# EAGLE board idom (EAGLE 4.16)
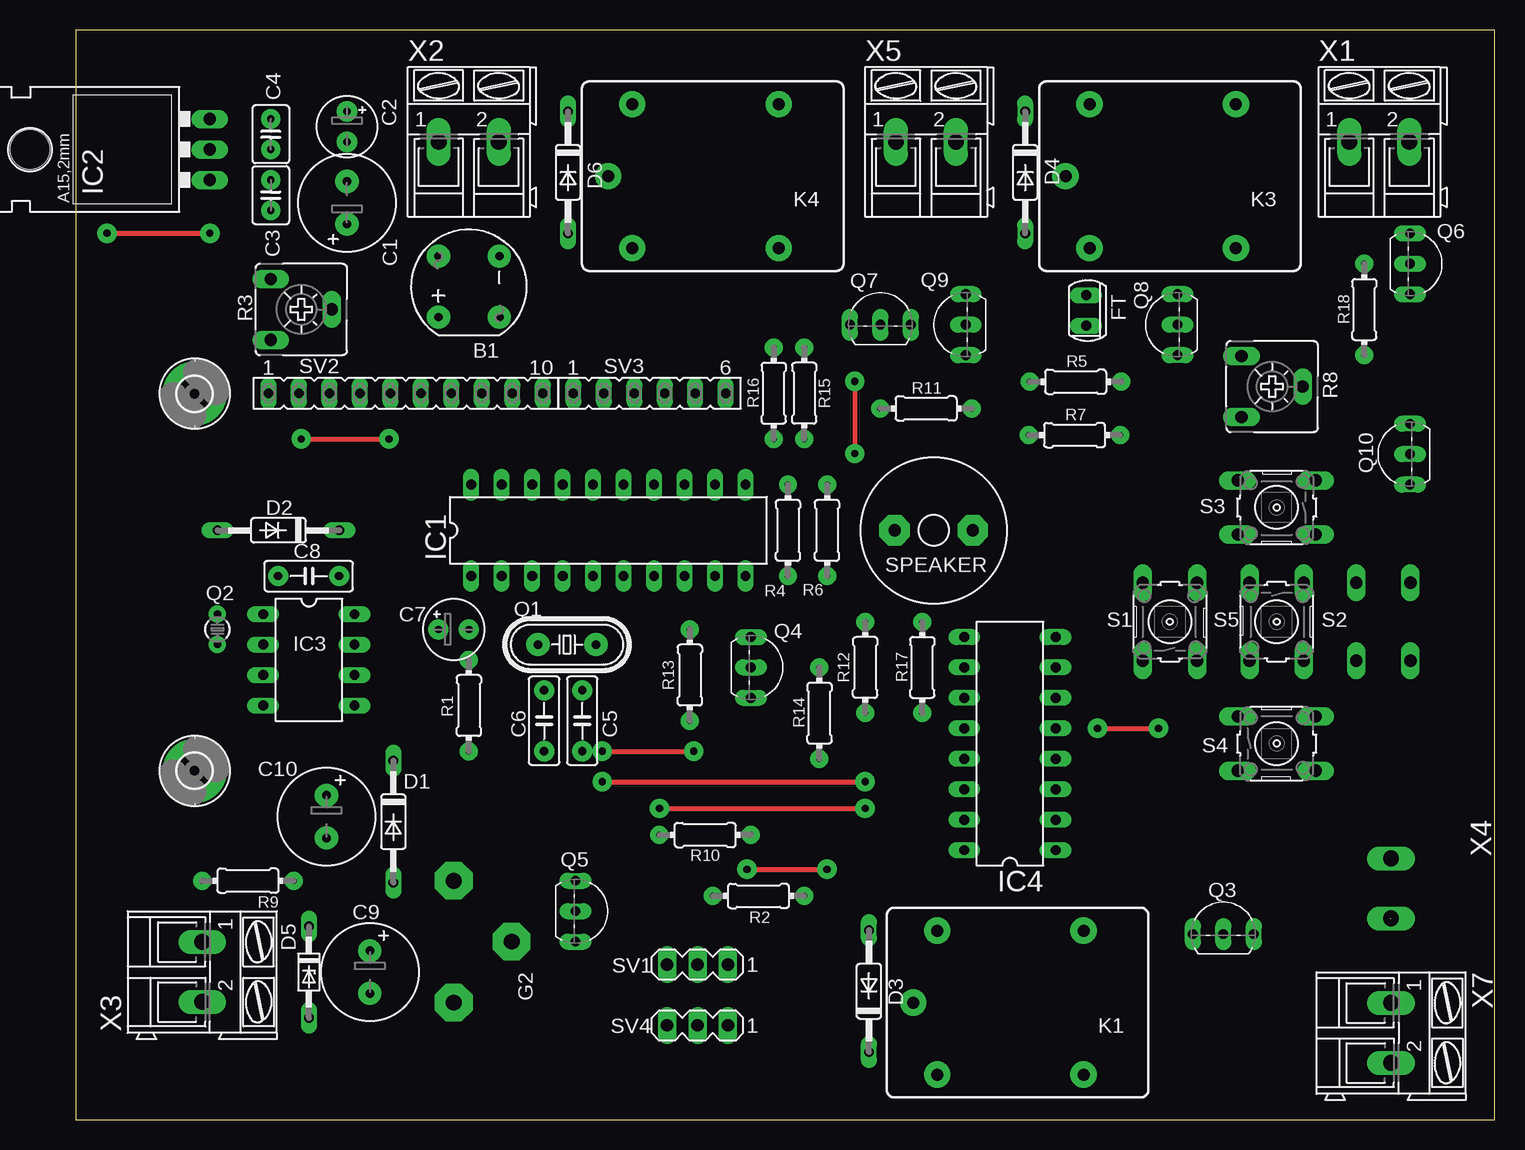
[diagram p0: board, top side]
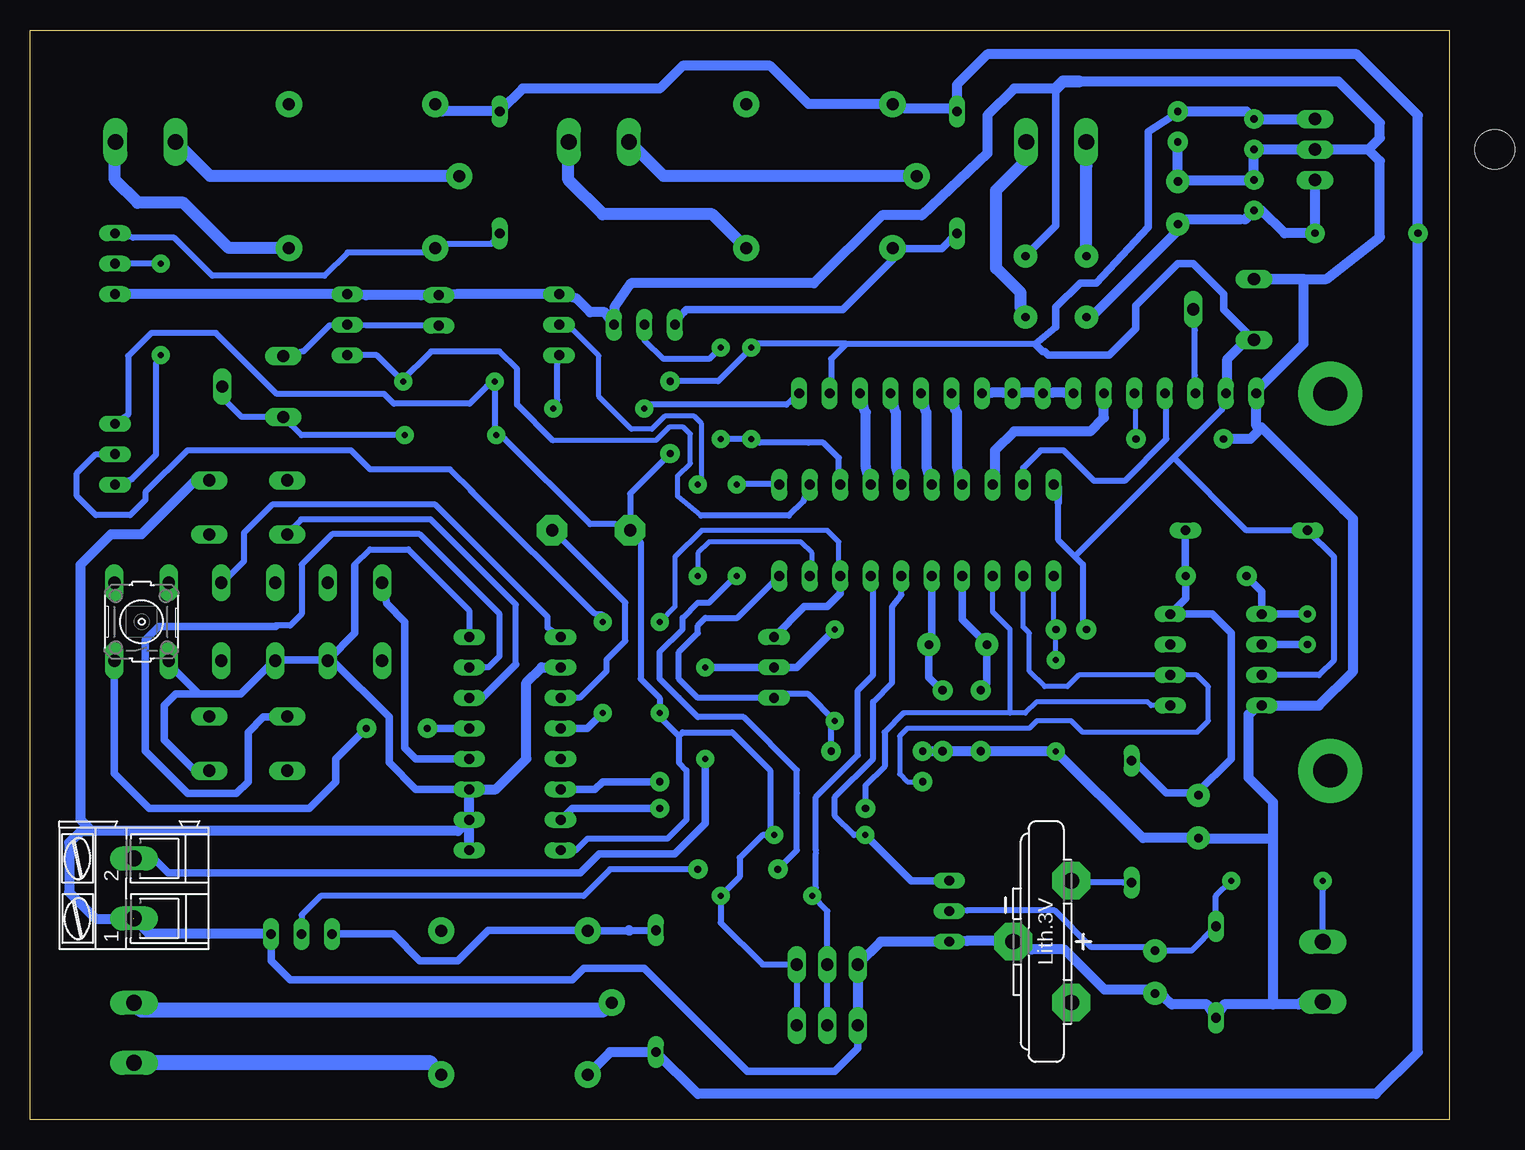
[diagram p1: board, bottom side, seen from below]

Size 118.27 x 90.86 mm. Coordinates in mm from the lower left corner, seen from the top.
Outline: 0,0 118.27,0 118.27,90.86 0,90.86 0,0
Copper layers (1*16): Top 0.035mm / dielectric 1.5mm / Bottom 0.035mm
Design rules "mój": minimum track width 20mil, minimum drill 15mil, track to track 25mil, track to pad 30mil, pad to pad 25mil, via to via 25mil, smd to smd 20mil, copper to edge 20mil, drill to drill 20mil, minimum pad ring 10mil, minimum via ring 20mil, stop-mask expansion 4mil, vias tented up to drill 0mil, thermal gap 10mil
Net classes: 1 1mm: width 1 mm, drill 1 mm; 2 2mm: width 2 mm, drill 2 mm

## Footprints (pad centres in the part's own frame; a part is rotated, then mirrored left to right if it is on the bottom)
2,8-PAD = drill 2.8 pad 5.334 round: B2,8 0,0
RB1A = drill 0.7 pad 1.93 round: + -2.54,2.54; - 2.54,-2.54; AC1 2.54,2.54; AC2 -2.54,-2.54
E3,5-8 = drill 0.7 pad 1.93 round: + -1.778,0; - 1.778,0
E2,5-5 = drill 0.6 pad 1.676 round: + -1.27,0; - 1.27,0
C2.5-3 = drill 0.6 pad 1.6 round: 1 -1.27,0; 2 1.27,0
C5B2.5 = drill 0.7 pad 1.676 round: 1 -2.54,0; 2 2.54,0
DO35-10 = drill 0.813 long: A 5.08,0; C -5.08,0
DO34Z7 = drill 0.813 long: A 3.81,0; C -3.81,0
SFH225 = drill 0.813 long: A 0,1.27; K 0,-1.27
CR2032V = drill 1.321 pad 3.15 octagon: + -2.54,-5.08; +@1 -2.54,5.08; - 2.286,0
DIL20 = drill 0.813 long: 1 -11.43,-3.81; 2 -8.89,-3.81; 3 -6.35,-3.81; 4 -3.81,-3.81; 5 -1.27,-3.81; 6 1.27,-3.81; 7 3.81,-3.81; 8 6.35,-3.81; 9 8.89,-3.81; 10 11.43,-3.81; 11 11.43,3.81; 12 8.89,3.81; 13 6.35,3.81; 14 3.81,3.81; 15 1.27,3.81; 16 -1.27,3.81; 17 -3.81,3.81; 18 -6.35,3.81; 19 -8.89,3.81; 20 -11.43,3.81
78XXL = drill 1.016 long: GND 0,-3.81; IN -2.54,-3.81; OUT 2.54,-3.81 | hole 3.302: 0,11.176
DIL08 = drill 0.813 long: 1 -3.81,-3.81; 2 -1.27,-3.81; 3 1.27,-3.81; 4 3.81,-3.81; 5 3.81,3.81; 6 1.27,3.81; 7 -1.27,3.81; 8 -3.81,3.81
DIL16 = drill 0.813 long: 1 -8.89,-3.81; 2 -6.35,-3.81; 3 -3.81,-3.81; 4 -1.27,-3.81; 5 1.27,-3.81; 6 3.81,-3.81; 7 6.35,-3.81; 8 8.89,-3.81; 9 8.89,3.81; 10 6.35,3.81; 11 3.81,3.81; 12 1.27,3.81; 13 -1.27,3.81; 14 -3.81,3.81; 15 -6.35,3.81; 16 -8.89,3.81
JS-M = drill 1 pad 2.184 round: 1 6.7,6; 2 6.7,-6; C 8.7,0; NC -5.5,-6; NO -5.5,6
HC49/S = drill 0.7 pad 1.93 round: 1 -2.413,0; 2 2.413,0
TC26V = drill 0.6 pad 1.422 round: 1 -1.27,0; 2 1.27,0
TO92-EBC = drill 0.813 long: B 0,-1.27; C -2.54,-1.27; E 2.54,-1.27
0204/7 = drill 0.5 pad 1.499 round: 1 -3.81,0; 2 3.81,0
CA6V = drill 1.016 long: A -2.54,-2.54; E 2.54,-2.54; S 0,2.54
B3F-10XX = drill 1.016 long: 1 -3.251,2.261; 2 3.251,2.261; 3 -3.251,-2.261; 4 3.251,-2.261
AL60P = drill 1.016 pad 2.54 octagon: 1 -3.251,0; 2 3.251,0
MA03-1 = drill 1.016 long: 1 -2.54,0; 2 0,0; 3 2.54,0
FE10 = drill 0.813 long: 1 -11.43,0; 2 -8.89,0; 3 -6.35,0; 4 -3.81,0; 5 -1.27,0; 6 1.27,0; 7 3.81,0; 8 6.35,0; 9 8.89,0; 10 11.43,0
FE06 = drill 0.813 long: 1 -6.35,0; 2 -3.81,0; 3 -1.27,0; 4 1.27,0; 5 3.81,0; 6 6.35,0
AK300/2 = drill 1.321 long: 1 -2.515,0; 2 2.489,0

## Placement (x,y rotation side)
.  [2,8-PAD]  9.91,60.53 0 top
B1  mostek 1A  [RB1A]  32.77,69.46 90 top
C1  470uF  [E3,5-8]  22.61,76.45 90 top
C2  100uF  [E2,5-5]  22.61,82.8 270 top
C3  100nF  [C2.5-3]  16.27,77.08 90 top
C4  100nF  [C2.5-3]  16.27,82.16 270 top
C5  33pF  [C5B2.5]  42.22,33.27 90 top
C6  33pF  [C5B2.5]  39.05,33.27 90 top
C7  10uF  [E2,5-5]  31.5,40.89 0 top
C8  33pF  [C5B2.5]  19.42,45.33 0 top
C9  10uF  [E3,5-8]  24.52,12.31 270 top
C10  22uF  [E3,5-8]  20.9,25.27 270 top
D1  1N4148  [DO35-10]  26.47,24.85 270 top
D2  1N4148  [DO35-10]  16.9,49.14 180 top
D3  1N4148  [DO35-10]  66.11,10.73 90 top
D4  1N4148  [DO35-10]  79.13,78.99 270 top
D5  4.7V  [DO34Z7]  19.44,12.31 270 top
D6  1N4148  [DO35-10]  41.03,78.99 270 top
FT  fotorezystor  [SFH225]  84.21,67.48 0 top
G2  CR2032V  [CR2032V]  34.05,14.85 180 bottom
IC1  AT89C4051P  [DIL20]  44.39,49.14 0 top
IC2  7805  [78XXL]  7.37,80.89 90 top
IC3  PFC8583P  [DIL08]  19.44,38.35 270 top
IC4  PCF8574AP  [DIL16]  77.86,31.36 90 top
K1  JQC-3FF  [JS-M]  78.5,9.77 180 top
K3  JQC-3FF  [JS-M]  91.19,78.67 180 top
K4  JQC-3FF  [JS-M]  53.09,78.67 180 top
Q1  11.059MHz  [HC49/S]  40.95,39.62 0 top
Q2  32768 Hz  [TC26V]  11.82,40.89 90 top
Q3  BC548  [TO92-EBC]  95.64,16.76 0 top
Q4  BC548  [TO92-EBC]  57.54,37.71 270 top
Q5  BC548  [TO92-EBC]  42.94,17.39 270 top
Q6  BC548  [TO92-EBC]  112.47,71.37 270 top
Q7  BC548  [TO92-EBC]  67.06,67.56 0 top
Q8  BC548  [TO92-EBC]  90.56,66.29 90 top
Q9  BC337  [TO92-EBC]  72.91,66.29 90 top
Q10  BC560  [TO92-EBC]  109.93,55.49 90 top
R1  10K  [0204/7]  32.77,34.54 90 top
R2  4.7K  [0204/7]  56.91,18.66 180 top
R3  10K  [CA6V]  18.8,67.56 270 top
R4  4.7K  [0204/7]  59.37,49.14 90 top
R5  1K  [0204/7]  83.34,61.53 180 top
R6  4.7K  [0204/7]  62.62,49.14 90 top
R7  100K (dobrac)  [0204/7]  83.24,57.08 180 top
R8  10K  [CA6V]  99.7,61.13 270 top
R9  4.7K  [0204/7]  14.36,19.93 180 top
R10  1K  [0204/7]  52.46,23.74 0 top
R11  9ohm lub zworka  [0204/7]  70.88,59.3 180 top
R12  1K  [0204/7]  65.8,37.71 90 top
R13  4.7K  [0204/7]  51.19,37.08 90 top
R14  10K  [0204/7]  61.98,33.9 270 top
R15  4.7K  [0204/7]  60.71,60.57 90 top
R16  1K  [0204/7]  58.17,60.57 270 top
R17  2.2K  [0204/7]  70.56,37.71 270 top
R18  2.2K  [0204/7]  107.39,67.56 270 top
S1  Prev  [B3F-10XX]  91.19,41.52 90 top
S2  Next  [B3F-10XX]  108.97,41.52 90 bottom
S3  plus  [B3F-10XX]  100.09,51.05 180 top
S4  minus  [B3F-10XX]  100.09,31.36 0 top
S5  OK  [B3F-10XX]  100.09,41.52 270 top
SPEAKER  AL60P  [AL60P]  71.51,49.14 180 top
SV1  termometr wewn.  [MA03-1]  51.82,12.95 180 top
SV2  [FE10]  27.5,60.57 0 top
SV3  [FE06]  47.82,60.57 0 top
SV4  termometr zewn.  [MA03-1]  51.82,7.87 180 top
X1  [AK300/2]  108.66,81.53 0 top
X2  [AK300/2]  32.77,81.53 0 top
X3  [AK300/2]  10.55,12.31 270 top
X4  [AK300/2]  109.61,19.3 90 bottom
X5  [AK300/2]  70.88,81.53 0 top
X7  [AK300/2]  109.61,7.23 270 top
~  [2,8-PAD]  9.91,29.1 0 top

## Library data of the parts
. ~ = holes
B1 = rectifier
C1 C2 C7 C9 C10 R1 R2 R4-R7 R9-R18 = rcl
C3-C6 C8 = capacitor-wima
D1-D6 = diode
FT = opto-trans-siemens
G2 = battery
IC1 = atmel
IC2 = v-reg
IC3 IC4 = micro-philips
K1 K3 K4 = relay
Q1 Q2 = crystal
Q3-Q9 = transistor-npn
Q10 = transistor-pnp
R3 R8 = pot
S1-S5 = switch-omron
SPEAKER = buzzer
SV1 SV4 = con-lstb
SV2 SV3 = con-lsta
X1-X5 X7 = con-ptr500

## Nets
N$1: D6.A K4.1 Q7.C
N$2: IC1.19 SV2.4
N$3: IC1.18 SV2.6
N$4: IC1.12 Q8.C R5.1
N$5: IC1.17 SV3.1
N$6: C5.2 IC1.5 Q1.2
N$7: C6.2 IC1.4 Q1.1
N$8: IC1.16 SV3.2
N$9: C7.- IC1.1 R1.2
N$10: IC1.15 SV3.3
N$11: IC1.14 SV3.4
N$12: SV2.7 SV2.8 SV2.9 SV2.10
N$13: R3.S SV2.3
N$14: IC3.2 Q2.1
N$15: C8.1 IC3.1 Q2.2
N$16: Q3.B R4.1
N$17: D1.A G2.+
N$18: C8.2 C10.+ D1.C D2.C IC3.8
N$19: IC1.11 R4.2
N$20: IC1.2 IC3.6 IC4.14
N$21: IC1.3 IC3.5 IC4.15
N$22: D3.A K1.2 Q3.C
N$23: Q9.B R6.2
N$24: IC1.9 R6.1
N$25: Q9.C R11.1
N$26 [1mm]: K1.C X7.1
N$27 [1mm]: K1.NO X7.2
N$28 [1mm]: K3.C X1.1
N$29: IC4.4 S1.2
N$30 [1mm]: B1.AC1 X2.1
N$31 [1mm]: B1.AC2 X2.2
N$32: IC4.5 S2.1
N$33: IC4.6 S3.2
N$34: IC4.7 S4.1
N$35: IC4.9 S5.1
N$36: R11.2 SV3.6
N$37: R7.1 R8.E R8.S
N$38: IC1.7 R2.2 SV1.2 SV4.2
N$39: IC1.8 Q4.C R12.2
N$40: IC1.6 Q5.C R10.1
N$41: C9.+ D5.C Q5.B R9.1
N$42: Q4.B R13.2 R14.1
N$43: R9.2 X3.1
N$44: C2.+ C4.1 C7.+ D2.A IC1.20 IC2.OUT IC3.3 IC4.16 Q10.E R2.1 R3.E R5.2 R7.2 R10.2 R12.1 R16.1 SPEAKER.2 SV1.1 SV2.2 SV3.5 SV4.1
N$45: R14.2 X4.2
N$46: B1.+ C1.+ C3.1 D3.C D4.C D6.C IC2.IN K1.1 K3.2 K4.2
N$47: B1.- C1.- C2.- C3.2 C4.2 C5.1 C6.1 C9.- C10.- D5.A FT.A G2.- IC1.10 IC2.GND IC3.4 IC4.1 IC4.2 IC4.3 IC4.8 IC4.10 Q3.E Q4.E Q5.E Q6.E Q7.E Q8.E Q9.E R1.1 R3.A R13.1 S1.3 S2.3 S3.3 S4.4 S5.4 SV1.3 SV2.1 SV2.5 SV4.3 X3.2 X4.1
N$48: Q7.B R15.2
N$49 [1mm]: K4.NO X5.2
N$50 [1mm]: K4.C X5.1
N$51: IC1.13 R15.1 R16.2
N$52: IC4.12 R17.2
N$53: FT.K Q8.B R8.A
N$54: Q10.B R17.1
N$55 [1mm]: K3.NO X1.2
N$56: Q10.C R18.2
N$57: Q6.B R18.1
N$58: D4.A K3.1 Q6.C
N$59: IC4.11 SPEAKER.1

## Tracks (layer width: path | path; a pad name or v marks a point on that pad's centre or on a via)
N$1
  Bottom 0.508: 63.76,67.33 Q7.C
  Bottom 0.61: D6.A 42.3,72.64 46.36,72.64 K4.1 46.39,71.72 50.55,67.56 63.57,67.56 63.76,67.37 63.76,67.33
N$2
  Bottom 0.406: 23.57,60.57 SV2.4
  Bottom 0.508: IC1.19 35.5,54.35 34.05,55.81 32.14,55.81 29.6,53.27 27.06,53.27 23.57,56.76 23.57,60.57
N$3
  Bottom 0.813: SV2.6 28.77,58.54 29.92,57.4 36.27,57.4 37.86,55.81 37.86,52.95 IC1.18
N$4
  Bottom 0.406: 77.66,59.62 77.67,59.61 77.68,59.61 | 62.38,50.36 64.31,51.98 64.31,53.7 63.25,54.73 63.25,57.18 63.82,57.75 65.01,57.75 66.11,56.65 74.69,56.65 | 87.38,61.53 R5.1
  Bottom 0.508: IC1.12 53.81,51.58 55.02,50.36 62.38,50.36 | 74.69,56.65 77.66,59.62 | 77.68,59.61 77.68,62.62 79.13,64.07 84.84,64.07 87.38,61.53 | R5.1 89.37,63.75 Q8.C
N$5
  Bottom 0.508: 41,59 41.11,59.1
  Bottom 0.813: 41,59 41,54.43 IC1.17 | 41.11,59.1 SV3.1
N$6
  Bottom 0.406: Q1.2 43.25,39.62 43.12,39.75 | C5.2 42.3,35.81
  Bottom 0.61: 43.12,39.75 IC1.5 | Q1.2 43.36,36.87 42.3,35.81
N$7
  Bottom 0.406: Q1.1 38.49,39.62 | C6.2 39.12,35.81
  Bottom 0.61: IC1.4 40.59,41.71 38.49,39.62 | Q1.1 38.54,36.4 39.12,35.81
N$8
  Bottom 0.508: 43.55,59 43.65,59.1
  Bottom 0.813: 43.55,59 43.55,54.43 IC1.16 | 43.65,59.1 SV3.2
N$9
  Bottom 0.406: IC1.1 32.97,41.02 33.09,40.89 C7.- R1.2
N$10
  Bottom 0.508: 46.09,59 46.19,59.1
  Bottom 0.813: 46.09,59 46.09,54.43 IC1.15 | 46.19,59.1 SV3.3
N$11
  Bottom 0.508: 48.62,59 48.73,59.1
  Bottom 0.813: 48.62,59 48.62,54.43 IC1.14 | 48.73,59.1 SV3.4
N$12
  Bottom 0.813: SV2.7 32.06,60.62 33.08,60.62 SV2.8 34.6,60.62 35.62,60.62 SV2.9 37.14,60.62 38.16,60.62 SV2.10
N$13
  Bottom 0.508: SV2.3 21.19,62.05 21.19,65.81 R3.S
N$14
  Bottom 0.61: Q2.1 IC3.2
N$15
  Bottom 0.406: 16.9,45.33 C8.1
  Bottom 0.61: Q2.2 IC3.1 15.63,44.06 16.9,45.33
N$16  (via drill 0.6)
  Top 0.406: v55.95,20.89 v62.62,20.89
  Bottom 0.406: 59.45,45.33 R4.1
  Bottom 0.508: v62.62,20.89 69.92,20.89 72.14,18.66 94.05,18.66 95.64,17.08 Q3.B | 59.45,45.33 61.67,43.11 62.62,43.11 63.89,41.84 63.89,40.89 65.8,38.98 65.8,36.76 64.21,35.17 62.62,33.59 58.81,33.59 54.37,29.14 54.37,27.24 54.37,22.47 v55.95,20.89
N$17
  Bottom 0.508: D1.A 27.19,19.78 30.03,19.78 G2.+
N$18
  Bottom 0.406: 21.03,27.24 20.91,27.11 C10.+ | 26.43,30.09 26.47,30.05 D1.C | C8.2 21.98,45.33
  Bottom 0.61: 26.43,30.09 23.57,27.24 21.03,27.24 18.17,30.09 18.17,40.57 19.76,42.16 IC3.8 21.96,43.45 C8.2 | 21.98,45.33 D2.C
N$19
  Bottom 0.508: IC1.11 56.55,53.01 58.58,53.01 R4.2
N$20  (via drill 0.6)
  Top 0.406: v43.89,28.19 v65.8,28.19
  Bottom 0.406: IC1.2 35.5,41.08 35,40.57 35,37.4 33.73,36.13 31.82,36.13 30.87,37.08 IC3.6 21.03,37.08 20.07,36.13 20.07,33.27 21.03,32.32 30.55,32.32 31.5,33.27 34.36,33.27 35,32.63 45.16,32.63 45.79,32 45.79,28.82 45.16,28.19 v43.89,28.19
  Bottom 0.61: IC4.14 71.19,27.55 70.56,28.19 v65.8,28.19
N$21  (via drill 0.6)
  Top 0.406: v48.65,25.97 v65.8,25.97
  Bottom 0.406: 36.59,33.9 35.31,33.9 34.36,34.86 25.16,34.86 24.84,34.54 IC3.5 | 36.59,33.9 45.48,33.9 | IC1.3 38.05,42.35 36.59,40.89 36.59,33.9
  Bottom 0.508: 45.48,33.9 47.06,32.32 47.06,29.46 48.65,27.87 v48.65,25.97
  Bottom 0.61: IC4.15 73.1,25.97 v65.8,25.97
N$22
  Bottom 0.61: D3.A 68.3,15.77 | Q3.C 88.02,15.49 85.8,13.27 82.62,13.27 80.08,15.81 71.83,15.81 | 68.37,15.77 K1.2
  Bottom 0.813: K1.2 71.83,15.81 | 68.3,15.77 68.34,15.81 68.37,15.77
N$23
  Bottom 0.406: Q9.B 74.05,66.29 74.01,66.33 73.5,66.33 70.88,63.7 70.88,60.31 68.15,57.58 66.45,57.58 65.37,58.67 62.94,58.67 62.3,58.03 62.3,53.27 R6.2
N$24
  Bottom 0.406: R6.1 62.62,47.24 61.67,48.19 54.05,48.19 53.09,47.24 53.09,45.33 IC1.9
N$25
  Bottom 0.508: Q9.C 74.33,63.06 74.33,60.02 R11.1
N$26
  Bottom 0.813: K1.C 69.92,9.77
  Bottom 1.27: X7.1 109,9.14 70.56,9.14 69.92,9.77
  Bottom 1.422: K1.C 69.6,9.77
N$27
  Bottom 0.813: 83.93,3.77 84.9,4.75
  Bottom 1.27: K1.NO 83.93,3.77 | 84.9,4.75 X7.2
  Bottom 1.422: 83.93,3.77 83.89,3.74
N$28
  Bottom 0.813: 106.12,81.53 X1.1
  Bottom 1.016: K3.C 103.26,78.67 106.12,81.53
N$29
  Bottom 0.61: S1.2 88.55,43.05 87.03,41.52 87.03,31.01 86.12,30.09 IC4.4
N$30
  Bottom 1: B1.AC1 30.23,79.52 X2.1
N$31
  Bottom 1: B1.AC2 35.72,67.74 35.72,68.96 37.75,70.99 37.75,77.49 35.09,80.16 X2.2
N$32  (via drill 0.6)
  Top 0.406: v85.16,32.63 v90.24,32.63
  Bottom 0.61: S2.1 111.24,28.86 108.34,25.97 95,25.97 92.78,28.19 92.78,30.09 v90.24,32.63 | IC4.5 v85.16,32.63
N$33
  Bottom 0.508: 77.78,37.97 77.78,42.95 84.9,50.06 95.68,50.06 96.91,48.83 96.87,48.79 S3.2
  Bottom 0.61: 77.78,37.97 80.58,35.17 IC4.6
N$34
  Bottom 0.406: 96.91,33.59 96.87,33.62 S4.1
  Bottom 0.508: IC4.7 80.08,37.71 79.13,38.67 79.13,42.16 85.8,48.83 93.1,48.83 95.64,46.29 95.64,42.16 96.59,41.21 97.86,41.21 97.86,41.12
  Bottom 0.61: 97.8,41.12 97.86,41.12 107.55,41.12 108.67,40 108.67,30.75 105.11,27.2 101.08,27.2 100.09,28.19 100.09,32.32 98.81,33.59 96.91,33.59
N$35
  Bottom 0.508: IC4.9 75.14,41.02 75.14,41.93 84.49,51.28 98.1,51.28 100.44,48.94 100.44,46.57 102.31,44.7 102.35,44.74 S5.1
N$36
  Bottom 0.508: SV3.6 55.24,59.61 66.62,59.61 R11.2
N$37
  Bottom 0.406: 97.23,58.67 97.16,58.6 R8.E | 102.31,61.21 102.24,61.14 R8.S
  Bottom 0.508: R7.1 95.64,57.08 97.16,58.6 | R8.E 100.64,58.59 102.31,60.26 102.31,61.21
N$38
  Bottom 0.406: 52.79,22.22 52.79,22.46 52.78,22.47
  Bottom 0.508: 52.79,22.22 52.79,19.38 R2.2 51.82,17.39 SV1.2 SV4.2 | 52.78,22.47 52.78,26.92 49.28,30.41 49.28,35.81 48.02,37.08 48.02,45.33 IC1.7
N$39
  Bottom 0.406: R12.2 64.53,42.79 64.53,46.92 62.3,49.14 51.82,49.14 50.87,48.19 50.87,45.33 IC1.8
  Bottom 0.61: IC1.8 50.74,43.87 51.82,42.79 53.73,42.79 Q4.C
N$40
  Bottom 0.406: IC1.6 45.79,45.33
  Bottom 0.508: R10.1 49.6,23.74 51.19,25.33 51.19,26.92 48.02,30.09 48.02,34.86 46.43,36.44 46.43,42.79 45.66,43.76 45.66,45.21 IC1.6
  Bottom 0.61: Q5.C 44.84,19.93 R10.1
N$41
  Bottom 0.508: Q5.B 40.19,17.45 32.88,17.45 29.83,14.4 25.26,14.4 C9.+ 21.47,14.09 D5.C 19.44,18.66 R9.1
N$42
  Bottom 0.61: R13.2 54.37,37.71 Q4.B R14.1
N$43
  Bottom 0.508: R9.2 10.52,19.17 10.52,15.82 X3.1
N$44  (via drill 0.6)
  Top 0.406: v64.93,61.57 v64.93,55.55
  Bottom 0.406: 58.13,64.37 58.14,64.38 R16.1 | 65.49,33.6 R12.1 65.8,33.59 | SPEAKER.2 68.34,49.14 | 72.78,22.47 IC4.16 | 33.73,64.07 33.88,64.07 | 51.82,60.57 SV3.5 | 50.25,64.69 50.24,64.7 | SV2.2 18.61,60.51 18.96,60.16 18.96,59.2
  Bottom 0.508: 23.23,83.59 C2.+ | 32.57,51.48 32.57,48.33 31.2,46.96 | 31.2,46.96 30.54,46.3 30.54,41.63 C7.+ | 22.96,55.2 18.96,59.2 | 22.96,55.2 31.2,46.96 | Q10.E 110.09,58.8 110.09,63.67 108.16,65.6 102.78,65.6 97.7,60.52 88.76,60.52 87.94,59.71 81.65,59.71 80.22,61.13 R5.2 79.51,60.83 79.51,57.78 R7.2 78.7,56.76 71.59,49.65 69.45,49.65 SPEAKER.2 68.26,52.21 v64.93,55.55 | v64.93,61.57 60.94,61.57 58.13,64.37 | R12.1 65.8,35.17 67.38,36.76 67.38,48.19 68.34,49.14 | 65.8,33.59 64.21,32 | 72.78,22.47 71.83,23.43 65.16,23.43 63.57,25.01 63.57,29.14 64.21,29.78 64.21,32 | 22.96,55.2 16.9,49.14 D2.A | D2.A 11.44,49.14 | IC3.3 10.87,37.08 9.6,38.35 9.6,46.92 D2.A | SV4.1 SV1.1 57.22,12.95 60.71,16.44 R2.1 59.13,20.25 59.13,21.84 57.22,23.74 56.59,23.74 56.59,29.14 59.76,32.32 63.89,32.32 64.21,32 | 34.5,64.69 50.25,64.69 51.51,63.43 51.51,60.89 51.82,60.57 | R16.1 57.86,64.7 50.24,64.7
  Bottom 0.61: 23.23,83.59 25.08,82.37 25.08,74.43 29.42,69.77 30.77,69.77 32.8,67.74 32.8,66.07 34.5,64.69 33.88,64.07 | R3.E 18.8,67.56 18.8,68.83 21.34,71.37 22.61,71.37 26.11,67.88 26.11,65.97 28.33,63.75 33.41,63.75 33.73,64.07 | IC1.20 32.77,52.95 32.57,52.75 32.57,51.48
  Bottom 0.813: C2.+ 16.9,84.07 C4.1 IC2.OUT | R3.E 16.9,65.02 18.49,63.43 18.49,60.57 SV2.2
  Bottom 1.016: 56.59,23.74 R10.2
N$45
  Bottom 0.406: 109.61,21.84 X4.2
  Bottom 0.61: R14.2 61.98,24.7 64.53,22.16 70.84,22.16 72.4,20.59 106.74,20.59 107.98,21.84 109.61,21.84
N$46  (via drill 0.6)
  Top 0.406: v2.61,73.91 v11.18,73.91
  Bottom 0.406: 17.03,75.05 17.43,75.05 | K3.2 84.81,84.67
  Bottom 0.813: 17.43,75.05 21.9,75.05 C1.+ 22.82,73.93 29.83,66.92 B1.+ | IC2.IN v11.18,73.91 13.72,73.91 15.63,75.81 C3.1 17.03,75.05 | 84.53,84.7 K3.2 83.89,84.07 D4.C 77.22,85.97 65.8,85.97 63.89,87.88 56.59,87.88 53.38,84.67 K4.2 45.37,84.3 41.72,84.3 D6.C 41.03,86.29 38.49,88.83 7.69,88.83 2.61,83.75 v2.61,73.91 2.61,5.65 6.1,2.15 62.62,2.15 D3.C 69.92,5.65 K1.1
N$47  (via drill 0.6)  (1 unrouted)
  Top 0.406: v43.89,30.73 v51.51,30.73 | v18.8,56.76 v26.11,56.76
  Bottom 0.406: 55.95,35.49 Q4.E | C5.1 43.57,30.73 v43.89,30.73 | 38.81,30.73 C6.1 39.36,30.73 | 93.02,38.27 S1.3 93.42,38.31 93.42,38.35 | SV2.5 26.11,60.45 v26.11,56.76 | 15.64,57.71 | 15.64,57.71 15.79,57.56 | 8.79,50.87 8.8,50.87 | 20.84,23.43 C10.- | 14.68,9.62 14.68,9.46 | 97.94,38.27 S5.4 97.82,38.35 97.86,38.35 | 106.75,38.03 106.71,38.07 | 113.1,24.07 113.1,24.06 | X3.2 10.55,9.77 | 12.4,9.77 12.56,9.62 | 51.51,32.95 R13.1
  Bottom 0.508: 15.64,57.71 15.71,57.78 | 113.1,24.07 113.14,24.07 | 55.95,35.49 53.41,35.49 R13.1 | IC1.10 59.32,41.84 61.98,41.84 62.62,41.21 62.62,40.57 64.21,38.98 64.21,36.76 62.62,35.17 Q4.E | v51.51,30.73 51.51,32.95 | IC4.8 81.67,42.48 86.75,47.56 89.93,47.56 91.19,46.29 91.19,46.2
  Bottom 0.61: 93.02,38.27 88.34,33.59 88.34,29.78 86.12,27.55 IC4.3 | B1.- 32.77,74.54 32.77,85.97 | 97.94,38.27 100.72,35.49 104.21,35.49 | 106.71,38.07 S2.3 106.75,38.23 106.75,38.03 104.21,35.49 | S4.4 104.49,29.1 107.07,31.68 107.07,34.54 106.12,35.49 104.21,35.49 | 91.19,46.2 91.19,40.57 93.42,38.35 | S1.3 93.46,38.35 97.82,38.35 | SV4.3 49.28,5.96 51.19,4.06 58.49,4.06 67.06,12.63 72.14,12.63 73.1,11.68 96.59,11.68 98.18,13.27 Q3.E | 109.61,16.76 X4.1
  Bottom 0.813: C2.- C1.- 21.9,78.3 17.03,78.3 C3.2 16.32,79.12 16.32,80.13 C4.2 IC2.GND | 8.8,50.87 15.64,57.71 15.63,57.72 | Q6.E 109.69,68.85 93.33,68.85 Q8.E 90.28,68.75 85.71,68.75 FT.A 82.66,68.85 75.65,68.85 Q9.E 72.7,68.45 71.59,67.33 70.37,67.33 Q7.E 69.57,67.74 68.19,69.74 52.94,69.74 47.27,75.42 43.96,75.42 38.49,80.58 38.49,83.75 36.27,85.97 32.77,85.97 | 12.56,9.62 14.68,9.62 | 14.68,9.62 18.75,9.62 D5.A 20.18,9.62 23.12,9.62 23.73,10.23 C9.- 25.26,10.84 28.71,10.84 32.06,14.19 34.81,14.19 G2.- 37.86,14.9 40.19,14.9 Q5.E 47.38,14.85 SV1.3 SV4.3 | 14.68,23.43 14.68,26.47 16.72,28.52 16.72,33.8 15.99,34.54 IC3.4 10.87,34.54 8.01,37.4 8.01,50.1 8.79,50.87 | 43.57,30.73 39.36,30.73 R1.1 25.54,23.5 C10.- | 30.87,86.56 9.23,86.56 5.79,83.12 5.79,81.85 6.74,80.89 | 6.74,80.89 5.79,79.94 5.79,73.59 10.23,70.1 R3.A 12.14,70.1 12.14,64.7 16.27,60.57 SV2.1 16.07,57.84 15.79,57.56 | v18.8,56.76 16.58,56.76 15.79,57.56 | 14.68,23.43 20.84,23.43 | 14.68,9.62 14.68,23.43 | Q3.E 108.34,15.49 109.61,16.76 112.78,16.76 115.01,18.98 115.01,23.11 114.06,24.06 113.1,24.06 114.06,25.01 114.06,46.29 111.51,48.83 108.97,48.83 104.49,53.31 S3.3 | 10.55,9.77 12.4,9.77 | IC2.GND 10.87,80.89 | 6.74,80.89 IC2.GND | 15.79,57.56 | IC4.10 75.64,37.71 76.91,36.44 76.91,30.09 79.45,27.55 IC4.3 IC4.2 | IC4.1 IC4.2 | 113.1,24.07 82.61,24.07 IC4.2
  Bottom 1.016: 30.87,86.56 32.19,86.56 32.77,85.97
N$48
  Bottom 0.508: R15.2 61.67,63.43 65.48,63.43 67.06,65.02 Q7.B
N$49
  Bottom 0.813: 73.41,81.53 X5.2
  Bottom 1.016: K4.NO 61.42,75.5 70.56,75.5 73.41,78.35 73.41,81.53
N$50
  Bottom 0.813: 68.34,81.53 X5.1
  Bottom 1.016: K4.C 65.48,78.67 68.34,81.53
N$51
  Bottom 0.406: IC1.13 50.55,52.95
  Bottom 0.508: R15.1 R16.2 57.46,56.46 53.4,56.46 52.16,56.46 50.87,55.18 50.87,53.27 50.55,52.95
N$52
  Bottom 0.61: R17.2 71.83,32.63 IC4.12
N$53
  Bottom 0.508: FT.K 85.71,66.21 90.28,66.21 Q8.B 93.33,66.21 95.46,64.08 R8.A
N$54
  Bottom 0.406: 81.36,52.31 81.35,52.32 | 81.36,52.31
  Bottom 0.508: R17.1 70.47,42.03 70.67,42.13 71.08,42.13 71.28,42.23 81.36,52.31 81.54,52.5 | Q10.B 112.78,55.49 114.37,53.91 114.37,52 112.78,50.41 109.93,50.41 108.66,51.68 108.66,52.32 105.16,55.81 91.51,55.81 89.93,54.22 83.26,54.22 81.35,52.32
N$55
  Bottom 0.813: 111.2,81.21 111.15,81.26 X1.2
  Bottom 1.016: K3.NO 101.71,72.67 105.48,76.45 109.29,76.45 111.2,78.35 111.2,81.21
N$56
  Bottom 0.508: R18.2 107.76,63.06 107.76,55.44 109.79,53.41 Q10.C
N$57
  Bottom 0.508: R18.1 108.16,71.39 109.69,71.39 Q6.B
N$58
  Bottom 0.508: D4.A 79.82,73.02 83.47,73.02 K3.1 85.5,72.31 91.81,72.31 93.73,70.38 103.08,70.38 106.23,73.53 109.69,73.53 Q6.C
N$59
  Bottom 0.406: 74.69,49.14 SPEAKER.1
  Bottom 0.508: IC4.11 72.46,35.17 70.24,37.4 70.24,38.35 68.65,39.94 68.65,43.11 74.69,49.14

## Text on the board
_tNames: X2 | X5 | X1 | C4 | C2 | D6 | D4 | IC2 | K4 | K3 | Q6 | C3 | C1 | Q7 | R3 | Q8 | R18 | FT | B1 | Q9 | R5 | R8 | SV2 | SV3 | R11 | R16 | R7 | R15 | Q10 | D2 | S3 | SP2 | IC1 | C8 | R4 | R6 | Q1 | S1 | S5 | C7 | Q4 | S2 | IC3 | R12 | R17 | Q2 | R13 | R14 | R1 | S4 | D1 | C6 | C5 | C10 | R10 | Q5 | IC4 | R9 | Q3 | X3 | R2 | D5 | SV1 | G2 | X7 | C9 | SV4 | K1 | D3
_bNames: X4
